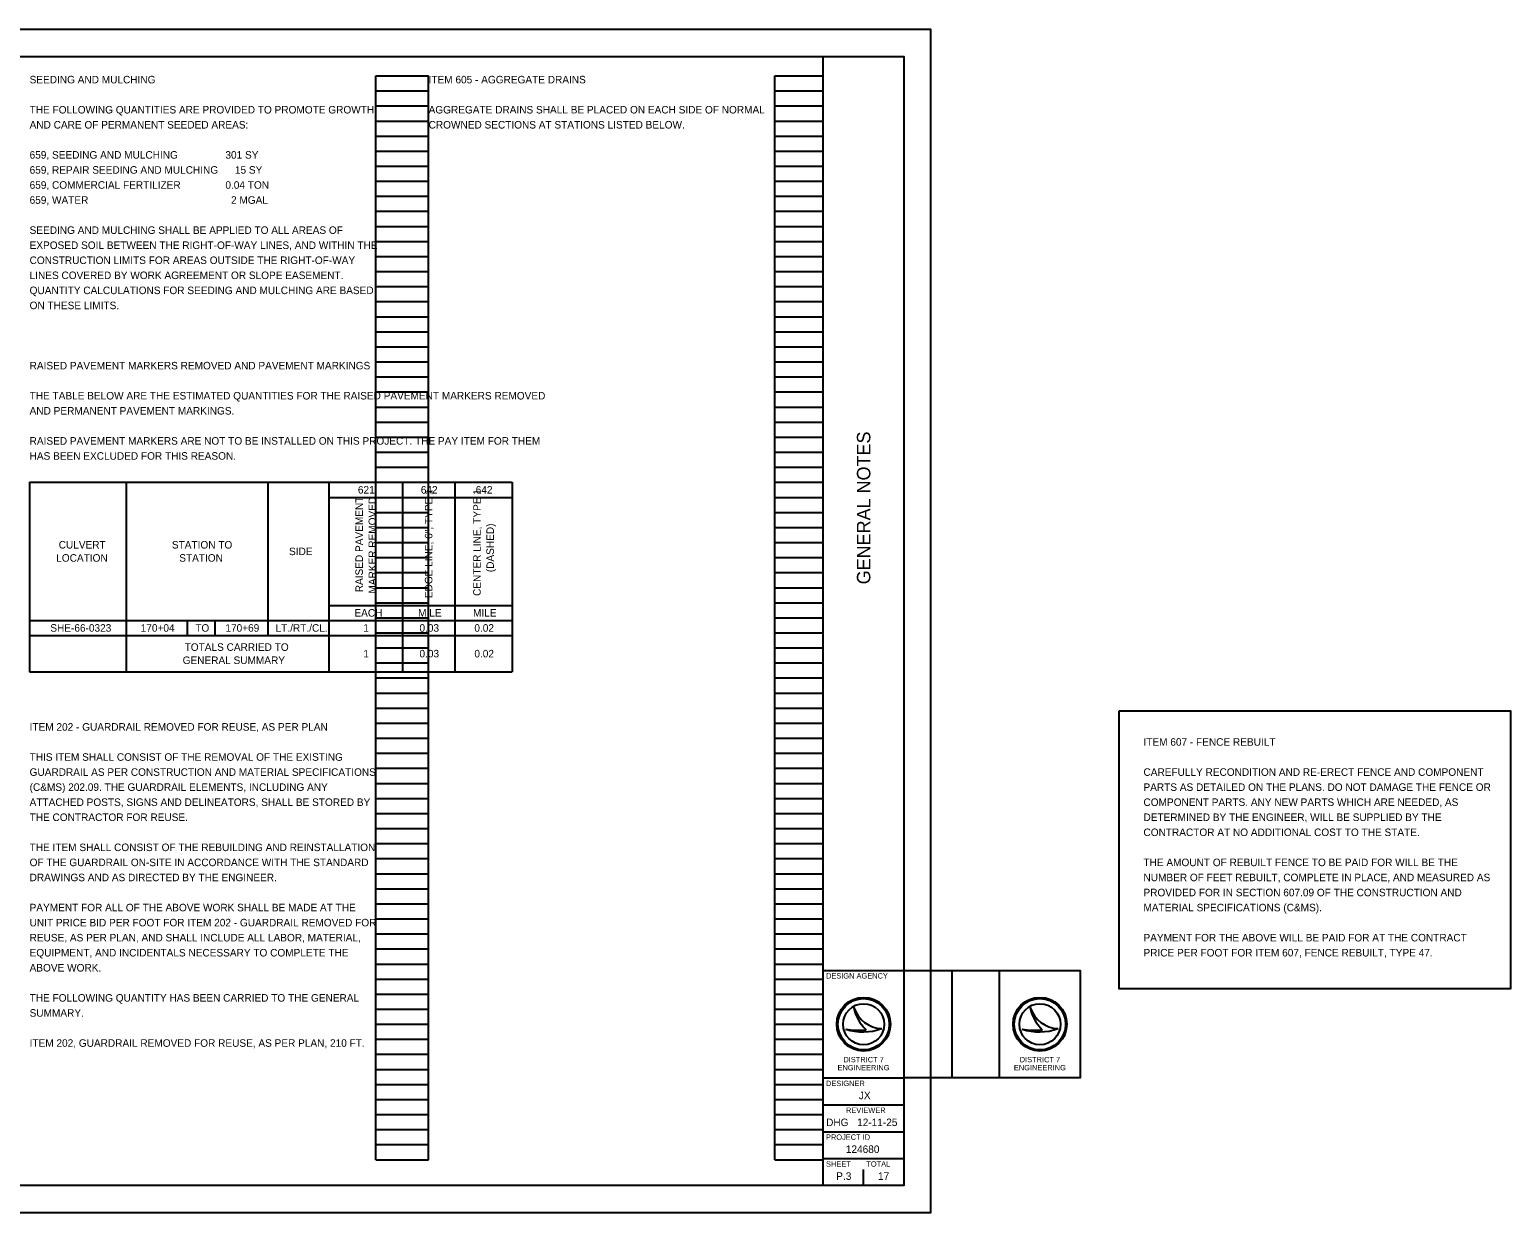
# Model space of a CAD drawing. Extents: x -7.4 to 44.8, y 0 to 22.
# Drawn here: x 17.24 to 44.78, y 0 to 22 of the extents above; entities that cross this region are included whole.
import ezdxf

# ---------------------------------------------------------------- set-up
doc = ezdxf.new("R2010")
doc.units = 0
for name, color, linetype in [('SC_Scratch1', 7, 'Continuous'), ('SH_Border', 7, 'Continuous'), ('SH_Cut_Line', 7, 'Continuous'), ('SH_Data', 7, 'Continuous'), ('SH_Text', 7, 'Continuous')]:
    doc.layers.add(name, color=color, linetype=linetype)

msp = doc.modelspace()

# ---------------------------------------------------------------- linework, layer by layer
at = {"layer": 'SC_Scratch1'}
for p, q in [((33.5, 4.5), (35.279, 4.5)), ((34.389, 4.5), (34.389, 2.5)), ((35.279, 2.5), (33.5, 2.5))]:
    msp.add_line(p, q, dxfattribs=at)
for points in [[(37.501, 9.328), (44.777, 9.328), (44.777, 4.157), (37.501, 4.157)], [(35.279, 4.5), (36.779, 4.5), (36.779, 2.5), (35.279, 2.5)]]:
    msp.add_lwpolyline(points, close=True, dxfattribs=at)
at = {"layer": 'SH_Border'}
for p, q in [((32, 0.5), (32, 21.5)), ((32, 4.5), (33.5, 4.5)), ((32, 2.5), (33.5, 2.5)), ((32, 2), (33.5, 2)), ((32, 1.5), (33.5, 1.5)), ((32, 1), (33.5, 1))]:
    msp.add_line(p, q, dxfattribs=at)
msp.add_lwpolyline([(1.5, 21.5), (33.5, 21.5), (33.5, 0.5), (1.5, 0.5)], close=True, dxfattribs=at)
at = {"layer": 'SH_Cut_Line'}
msp.add_lwpolyline([(0, 0), (34, 0), (34, 22), (0, 22)], close=True, dxfattribs=at)
at = {"layer": 'SH_Data'}
for p, q in [((23.68, 0.98), (23.68, 21.14)), ((23.68, 21.14), (24.66, 21.14)), ((24.66, 0.98), (24.66, 21.14)), ((31.1, 0.98), (31.1, 21.14)), ((31.1, 21.14), (32, 21.14)), ((32, 0.98), (32, 21.14)), ((23.68, 20.86), (24.66, 20.86)), ((31.1, 20.86), (32, 20.86)), ((23.68, 20.58), (24.66, 20.58)), ((31.1, 20.58), (32, 20.58)), ((23.68, 20.3), (24.66, 20.3)), ((31.1, 20.3), (32, 20.3)), ((23.68, 20.02), (24.66, 20.02)), ((31.1, 20.02), (32, 20.02)), ((23.68, 19.74), (24.66, 19.74)), ((31.1, 19.74), (32, 19.74)), ((23.68, 19.46), (24.66, 19.46)), ((31.1, 19.46), (32, 19.46)), ((23.68, 19.18), (24.66, 19.18)), ((31.1, 19.18), (32, 19.18)), ((23.68, 18.9), (24.66, 18.9)), ((31.1, 18.9), (32, 18.9)), ((23.68, 18.62), (24.66, 18.62)), ((31.1, 18.62), (32, 18.62)), ((23.68, 18.34), (24.66, 18.34)), ((31.1, 18.34), (32, 18.34)), ((23.68, 18.06), (24.66, 18.06)), ((31.1, 18.06), (32, 18.06)), ((23.68, 17.78), (24.66, 17.78)), ((31.1, 17.78), (32, 17.78)), ((23.68, 17.5), (24.66, 17.5)), ((31.1, 17.5), (32, 17.5)), ((23.68, 17.22), (24.66, 17.22)), ((31.1, 17.22), (32, 17.22)), ((23.68, 16.94), (24.66, 16.94)), ((31.1, 16.94), (32, 16.94)), ((23.68, 16.66), (24.66, 16.66)), ((31.1, 16.66), (32, 16.66)), ((23.68, 16.38), (24.66, 16.38)), ((31.1, 16.38), (32, 16.38)), ((23.68, 16.1), (24.66, 16.1)), ((31.1, 16.1), (32, 16.1)), ((23.68, 15.82), (24.66, 15.82)), ((31.1, 15.82), (32, 15.82)), ((23.68, 15.54), (24.66, 15.54)), ((31.1, 15.54), (32, 15.54)), ((23.68, 15.26), (24.66, 15.26)), ((31.1, 15.26), (32, 15.26)), ((23.68, 14.98), (24.66, 14.98)), ((31.1, 14.98), (32, 14.98)), ((23.68, 14.7), (24.66, 14.7)), ((31.1, 14.7), (32, 14.7)), ((23.68, 14.42), (24.66, 14.42)), ((31.1, 14.42), (32, 14.42)), ((23.68, 14.14), (24.66, 14.14)), ((31.1, 14.14), (32, 14.14)), ((23.68, 13.86), (24.66, 13.86)), ((31.1, 13.86), (32, 13.86)), ((17.24, 13.58), (26.216, 13.58)), ((17.24, 13.58), (17.24, 10.055)), ((19.035, 13.58), (19.035, 10.055)), ((21.671, 13.58), (21.671, 10.731)), ((22.807, 13.58), (22.807, 10.055)), ((23.68, 13.58), (24.66, 13.58)), ((24.174, 13.58), (24.174, 10.055)), ((25.146, 13.58), (25.146, 10.055)), ((26.216, 13.58), (26.216, 10.055)), ((31.1, 13.58), (32, 13.58)), ((22.807, 13.3), (26.216, 13.3)), ((23.68, 13.3), (24.66, 13.3)), ((31.1, 13.3), (32, 13.3)), ((23.68, 13.02), (24.66, 13.02)), ((31.1, 13.02), (32, 13.02)), ((23.68, 12.74), (24.66, 12.74)), ((31.1, 12.74), (32, 12.74)), ((23.68, 12.46), (24.66, 12.46)), ((31.1, 12.46), (32, 12.46)), ((23.68, 12.18), (24.66, 12.18)), ((31.1, 12.18), (32, 12.18)), ((23.68, 11.9), (24.66, 11.9)), ((31.1, 11.9), (32, 11.9)), ((23.68, 11.62), (24.66, 11.62)), ((31.1, 11.62), (32, 11.62)), ((22.807, 11.291), (26.216, 11.291)), ((23.68, 11.34), (24.66, 11.34)), ((31.1, 11.34), (32, 11.34)), ((23.68, 11.06), (24.66, 11.06)), ((31.1, 11.06), (32, 11.06)), ((17.24, 11.011), (26.216, 11.011)), ((20.172, 11.011), (20.172, 10.731)), ((20.682, 11.011), (20.682, 10.731)), ((23.68, 10.78), (24.66, 10.78)), ((31.1, 10.78), (32, 10.78)), ((17.24, 10.731), (26.216, 10.731)), ((23.68, 10.5), (24.66, 10.5)), ((31.1, 10.5), (32, 10.5)), ((23.68, 10.22), (24.66, 10.22)), ((31.1, 10.22), (32, 10.22)), ((17.24, 10.055), (26.216, 10.055)), ((23.68, 9.94), (24.66, 9.94)), ((31.1, 9.94), (32, 9.94)), ((23.68, 9.66), (24.66, 9.66)), ((31.1, 9.66), (32, 9.66)), ((23.68, 9.38), (24.66, 9.38)), ((31.1, 9.38), (32, 9.38)), ((23.68, 9.1), (24.66, 9.1)), ((31.1, 9.1), (32, 9.1)), ((23.68, 8.82), (24.66, 8.82)), ((31.1, 8.82), (32, 8.82)), ((23.68, 8.54), (24.66, 8.54)), ((31.1, 8.54), (32, 8.54)), ((23.68, 8.26), (24.66, 8.26)), ((31.1, 8.26), (32, 8.26)), ((23.68, 7.98), (24.66, 7.98)), ((31.1, 7.98), (32, 7.98)), ((23.68, 7.7), (24.66, 7.7)), ((31.1, 7.7), (32, 7.7)), ((23.68, 7.42), (24.66, 7.42)), ((31.1, 7.42), (32, 7.42)), ((23.68, 7.14), (24.66, 7.14)), ((31.1, 7.14), (32, 7.14)), ((23.68, 6.86), (24.66, 6.86)), ((31.1, 6.86), (32, 6.86)), ((23.68, 6.58), (24.66, 6.58)), ((31.1, 6.58), (32, 6.58)), ((23.68, 6.3), (24.66, 6.3)), ((31.1, 6.3), (32, 6.3)), ((23.68, 6.02), (24.66, 6.02)), ((31.1, 6.02), (32, 6.02)), ((23.68, 5.74), (24.66, 5.74)), ((31.1, 5.74), (32, 5.74)), ((23.68, 5.46), (24.66, 5.46)), ((31.1, 5.46), (32, 5.46)), ((23.68, 5.18), (24.66, 5.18)), ((31.1, 5.18), (32, 5.18)), ((23.68, 4.9), (24.66, 4.9)), ((31.1, 4.9), (32, 4.9)), ((23.68, 4.62), (24.66, 4.62)), ((31.1, 4.62), (32, 4.62)), ((23.68, 4.34), (24.66, 4.34)), ((31.1, 4.34), (32, 4.34)), ((23.68, 4.06), (24.66, 4.06)), ((31.1, 4.06), (32, 4.06)), ((23.68, 3.78), (24.66, 3.78)), ((31.1, 3.78), (32, 3.78)), ((32.567, 3.81), (32.567, 3.81)), ((35.846, 3.81), (35.846, 3.81)), ((23.68, 3.5), (24.66, 3.5)), ((31.1, 3.5), (32, 3.5)), ((32.417, 3.41), (32.417, 3.41)), ((32.75, 3.5), (32.75, 3.5)), ((33.087, 3.419), (33.087, 3.419)), ((35.696, 3.41), (35.696, 3.41)), ((36.366, 3.419), (36.366, 3.419)), ((23.68, 3.22), (24.66, 3.22)), ((31.1, 3.22), (32, 3.22)), ((23.68, 2.94), (24.66, 2.94)), ((31.1, 2.94), (32, 2.94)), ((23.68, 2.66), (24.66, 2.66)), ((31.1, 2.66), (32, 2.66)), ((23.68, 2.38), (24.66, 2.38)), ((31.1, 2.38), (32, 2.38)), ((23.68, 2.1), (24.66, 2.1)), ((31.1, 2.1), (32, 2.1)), ((23.68, 1.82), (24.66, 1.82)), ((31.1, 1.82), (32, 1.82)), ((23.68, 1.54), (24.66, 1.54)), ((31.1, 1.54), (32, 1.54)), ((23.68, 1.26), (24.66, 1.26)), ((31.1, 1.26), (32, 1.26)), ((23.68, 0.98), (24.66, 0.98)), ((31.1, 0.98), (32, 0.98)), ((32.375, 0.675), (32.375, 0.675)), ((32.75, 0.5), (32.75, 0.8))]:
    msp.add_line(p, q, dxfattribs=at)
for centre, radius in [((32.75, 3.5), 0.5), ((32.75, 3.5), 0.477), ((32.75, 3.5), 0.477), ((32.75, 3.5), 0.382), ((36.029, 3.5), 0.5), ((36.029, 3.5), 0.477), ((36.029, 3.5), 0.477), ((36.029, 3.5), 0.382)]:
    msp.add_circle(centre, radius, dxfattribs=at)
for centre, radius, start, end in [((33.116, 3.998), 0.58, 198.9257, 198.9319), ((33.347, 3.97), 0.796, 191.6379, 191.6421), ((33.116, 3.998), 0.58, 198.9319, 267.1657), ((33.347, 3.97), 0.796, 191.6421, 226.0947), ((36.395, 3.998), 0.58, 198.9257, 198.9319), ((36.625, 3.97), 0.796, 191.6379, 191.6421), ((36.395, 3.998), 0.58, 198.9319, 267.1657), ((36.625, 3.97), 0.796, 191.6421, 226.0947), ((32.739, 4.37), 1.013, 251.4576, 290.0832), ((32.648, 4.654), 1.266, 259.4964, 259.4995), ((32.739, 4.37), 1.013, 251.4527, 251.4576), ((32.648, 4.654), 1.266, 259.4995, 276.6672), ((36.018, 4.37), 1.013, 251.4576, 290.0832), ((35.927, 4.654), 1.266, 259.4964, 259.4995), ((36.018, 4.37), 1.013, 251.4527, 251.4576), ((35.927, 4.654), 1.266, 259.4995, 276.6672)]:
    msp.add_arc(centre, radius, start, end, dxfattribs=at)

# ---------------------------------------------------------------- texts
at = {"layer": 'SC_Scratch1'}
for s, p in [('ITEM 607 - FENCE REBUILT', (37.954, 8.68)), ('CAREFULLY RECONDITION AND RE-ERECT FENCE AND COMPONENT ', (37.954, 8.12)), ('PARTS AS DETAILED ON THE PLANS. DO NOT DAMAGE THE FENCE OR ', (37.954, 7.84)), ('COMPONENT PARTS. ANY NEW PARTS WHICH ARE NEEDED, AS ', (37.954, 7.56)), ('DETERMINED BY THE ENGINEER, WILL BE SUPPLIED BY THE ', (37.954, 7.28)), ('CONTRACTOR AT NO ADDITIONAL COST TO THE STATE. ', (37.954, 7)), ('THE AMOUNT OF REBUILT FENCE TO BE PAID FOR WILL BE THE ', (37.954, 6.44)), ('NUMBER OF FEET REBUILT, COMPLETE IN PLACE, AND MEASURED AS ', (37.954, 6.16)), ('PROVIDED FOR IN SECTION 607.09 OF THE CONSTRUCTION AND ', (37.954, 5.88)), ('MATERIAL SPECIFICATIONS (C&MS).', (37.954, 5.6)), ('PAYMENT FOR THE ABOVE WILL BE PAID FOR AT THE CONTRACT ', (37.954, 5.04)), ('PRICE PER FOOT FOR ITEM 607, FENCE REBUILT, TYPE 47.', (37.954, 4.76))]:
    msp.add_text(s, height=0.14, dxfattribs=at).set_placement(p)
at = {"layer": 'SH_Data'}
msp.add_text('GENERAL NOTES', height=0.25, rotation=90, dxfattribs=at).set_placement((32.875, 11.682))
for s, height, p in [('DESIGN AGENCY', 0.1, (32.05, 4.35)), ('DESIGNER', 0.1, (32.05, 2.35)), ('JX', 0.14, (32.661, 2.105)), ('REVIEWER', 0.1, (32.422, 1.85)), ('DHG', 0.14, (32.052, 1.605)), ('12-11-25', 0.14, (32.629, 1.605)), ('PROJECT ID', 0.1, (32.05, 1.35)), ('124680', 0.14, (32.419, 1.105)), ('SHEET', 0.1, (32.05, 0.85)), ('TOTAL', 0.1, (32.8, 0.85)), ('P.3', 0.14, (32.241, 0.605)), ('17', 0.14, (33.018, 0.605))]:
    msp.add_text(s, height=height, dxfattribs=at).set_placement(p)
at = {"layer": 'SH_Text'}
for s, height, p in [('SEEDING AND MULCHING', 0.14, (17.24, 21)), ('ITEM 605 - AGGREGATE DRAINS', 0.14, (24.66, 21)), ('THE FOLLOWING QUANTITIES ARE PROVIDED TO PROMOTE GROWTH ', 0.14, (17.24, 20.44)), ('AGGREGATE DRAINS SHALL BE PLACED ON EACH SIDE OF NORMAL ', 0.14, (24.66, 20.44)), ('AND CARE OF PERMANENT SEEDED AREAS:', 0.14, (17.24, 20.16)), ('CROWNED SECTIONS AT STATIONS LISTED BELOW. ', 0.14, (24.66, 20.16)), ('659, SEEDING AND MULCHING                 301 SY', 0.14, (17.24, 19.6)), ('659, REPAIR SEEDING AND MULCHING      15 SY', 0.14, (17.24, 19.32)), ('659, COMMERCIAL FERTILIZER                0.04 TON', 0.14, (17.24, 19.04)), ('659, WATER                                                   2 MGAL', 0.14, (17.24, 18.76)), ('SEEDING AND MULCHING SHALL BE APPLIED TO ALL AREAS OF ', 0.14, (17.24, 18.2)), ('EXPOSED SOIL BETWEEN THE RIGHT-OF-WAY LINES, AND WITHIN THE ', 0.14, (17.24, 17.92)), ('CONSTRUCTION LIMITS FOR AREAS OUTSIDE THE RIGHT-OF-WAY ', 0.14, (17.24, 17.64)), ('LINES COVERED BY WORK AGREEMENT OR SLOPE EASEMENT. ', 0.14, (17.24, 17.36)), ('QUANTITY CALCULATIONS FOR SEEDING AND MULCHING ARE BASED ', 0.14, (17.24, 17.08)), ('ON THESE LIMITS.', 0.14, (17.24, 16.8)), ('RAISED PAVEMENT MARKERS REMOVED AND PAVEMENT MARKINGS', 0.14, (17.24, 15.68)), ('THE TABLE BELOW ARE THE ESTIMATED QUANTITIES FOR THE RAISED PAVEMENT MARKERS REMOVED ', 0.14, (17.24, 15.12)), ('AND PERMANENT PAVEMENT MARKINGS. ', 0.14, (17.24, 14.84)), ('RAISED PAVEMENT MARKERS ARE NOT TO BE INSTALLED ON THIS PROJECT. THE PAY ITEM FOR THEM ', 0.14, (17.24, 14.28)), ('HAS BEEN EXCLUDED FOR THIS REASON.', 0.14, (17.24, 14)), ('621', 0.14, (23.345, 13.37)), ('642', 0.14, (24.515, 13.37)), ('642', 0.14, (25.536, 13.37)), ('CULVERT ', 0.14, (17.781, 12.348)), ('STATION TO', 0.14, (19.886, 12.348)), ('LOCATION', 0.14, (17.735, 12.103)), ('STATION', 0.14, (20.023, 12.103)), ('SIDE', 0.14, (22.064, 12.225)), ('EACH', 0.14, (23.28, 11.081)), ('MILE', 0.14, (24.465, 11.081)), ('MILE', 0.14, (25.486, 11.081)), ('SHE-66-0323', 0.14, (17.625, 10.801)), ('170+04', 0.14, (19.306, 10.801)), ('TO', 0.14, (20.321, 10.801)), ('170+69', 0.14, (20.881, 10.801)), ('LT./RT./CL.', 0.14, (21.815, 10.801)), ('1', 0.14, (23.446, 10.801)), ('0.03', 0.14, (24.49, 10.801)), ('0.02', 0.14, (25.511, 10.801)), ('TOTALS CARRIED TO', 0.14, (20.123, 10.445)), ('0.03', 0.14, (24.49, 10.323)), ('0.02', 0.14, (25.511, 10.323)), ('GENERAL SUMMARY', 0.14, (20.086, 10.2)), ('1', 0.14, (23.446, 10.323)), ('ITEM 202 - GUARDRAIL REMOVED FOR REUSE, AS PER PLAN', 0.14, (17.24, 8.96)), ('THIS ITEM SHALL CONSIST OF THE REMOVAL OF THE EXISTING ', 0.14, (17.24, 8.4)), ('GUARDRAIL AS PER CONSTRUCTION AND MATERIAL SPECIFICATIONS ', 0.14, (17.24, 8.12)), ('(C&MS) 202.09. THE GUARDRAIL ELEMENTS, INCLUDING ANY ', 0.14, (17.24, 7.84)), ('ATTACHED POSTS, SIGNS AND DELINEATORS, SHALL BE STORED BY ', 0.14, (17.24, 7.56)), ('THE CONTRACTOR FOR REUSE. ', 0.14, (17.24, 7.28)), ('THE ITEM SHALL CONSIST OF THE REBUILDING AND REINSTALLATION ', 0.14, (17.24, 6.72)), ('OF THE GUARDRAIL ON-SITE IN ACCORDANCE WITH THE STANDARD ', 0.14, (17.24, 6.44)), ('DRAWINGS AND AS DIRECTED BY THE ENGINEER.', 0.14, (17.24, 6.16)), ('PAYMENT FOR ALL OF THE ABOVE WORK SHALL BE MADE AT THE ', 0.14, (17.24, 5.6)), ('UNIT PRICE BID PER FOOT FOR ITEM 202 - GUARDRAIL REMOVED FOR ', 0.14, (17.24, 5.32)), ('REUSE, AS PER PLAN, AND SHALL INCLUDE ALL LABOR, MATERIAL, ', 0.14, (17.24, 5.04)), ('EQUIPMENT, AND INCIDENTALS NECESSARY TO COMPLETE THE ', 0.14, (17.24, 4.76)), ('ABOVE WORK.', 0.14, (17.24, 4.48)), ('THE FOLLOWING QUANTITY HAS BEEN CARRIED TO THE GENERAL ', 0.14, (17.24, 3.92)), ('SUMMARY. ', 0.14, (17.24, 3.64)), ('ITEM 202, GUARDRAIL REMOVED FOR REUSE, AS PER PLAN, 210 FT. ', 0.14, (17.24, 3.08)), ('DISTRICT 7', 0.1, (32.374, 2.792)), ('DISTRICT 7', 0.1, (35.653, 2.792)), ('ENGINEERING', 0.1, (32.265, 2.642)), ('ENGINEERING', 0.1, (35.544, 2.642))]:
    msp.add_text(s, height=height, dxfattribs=at).set_placement(p)
for s, p in [('RAISED PAVEMENT ', (23.438, 11.535)), ('MARKER REMOVED', (23.683, 11.51)), ('EDGE LINE, 6", TYPE 1', (24.73, 11.425)), ('CENTER LINE, TYPE 1', (25.629, 11.466)), ('(DASHED)', (25.874, 11.908))]:
    msp.add_text(s, height=0.14, rotation=90, dxfattribs=at).set_placement(p)

doc.saveas('drawing.dxf')
